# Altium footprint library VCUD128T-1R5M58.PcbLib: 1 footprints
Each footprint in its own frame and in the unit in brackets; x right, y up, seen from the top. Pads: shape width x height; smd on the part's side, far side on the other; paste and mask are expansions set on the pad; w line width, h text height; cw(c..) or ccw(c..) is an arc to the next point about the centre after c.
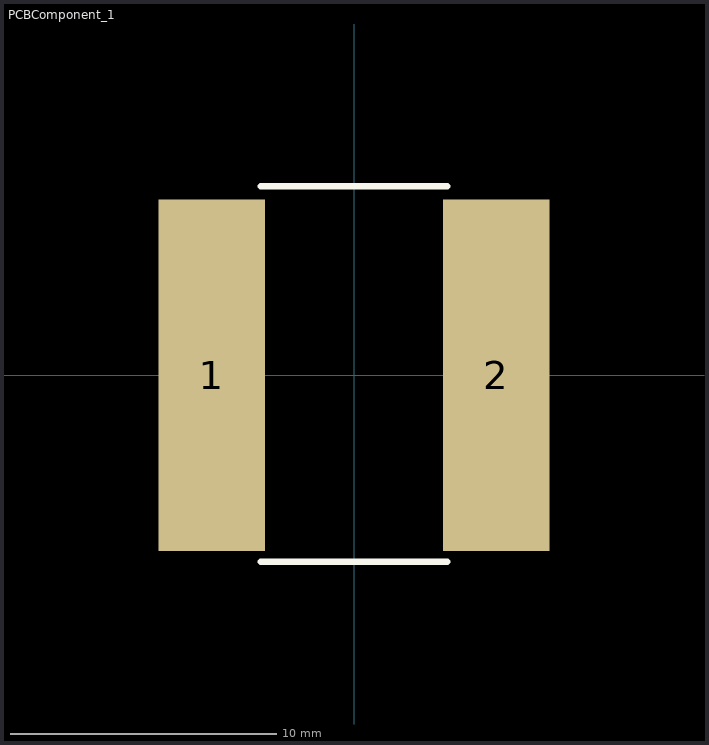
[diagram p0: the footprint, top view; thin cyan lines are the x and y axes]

## PCBComponent_1 [mm]
pads (2):
  rect 4x13.2 smd: 1(-5.35,0) 2(5.35,0)
Top Overlay:
  lines w0.254: -3.5,-7 3.5,-7 ; -3.5,7.1 3.5,7.1
M5 Assembly Top:
  text ".Designator" at -1.8,-0.514 h1.02
3D body: height 8, standoff 0, extent -6.7,-6.4 6.7,6.4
